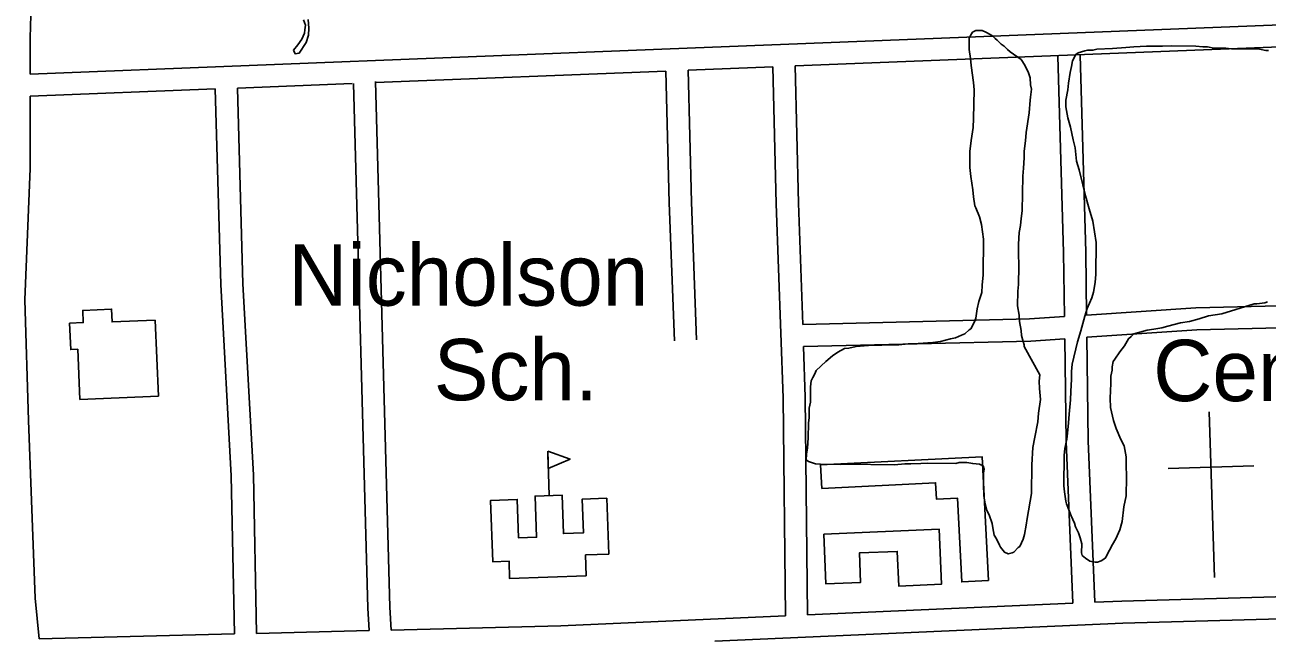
# Model space of a CAD drawing. Extents: x 3313447 to 3351316, y 703786 to 729172.
# Drawn here: x 3329082 to 3330764, y 710192 to 711026 of the extents above; entities that cross this region are included whole.
import ezdxf

# ---------------------------------------------------------------- set-up
doc = ezdxf.new("R2010")
doc.units = 0
for name, color, linetype in [('V-BLDG-IDEN', 7, 'Continuous'), ('V-BLDG-OTLN', 7, 'Continuous'), ('V-ROAD-CNTR', 7, 'Continuous'), ('V-SITE-OTLN', 7, 'Continuous'), ('V-SITE-OTLN-IDEN', 7, 'Continuous'), ('V-SITE-VEGE', 7, 'Continuous'), ('V-TOPO-SHOR', 7, 'Continuous')]:
    doc.layers.add(name, color=color, linetype=linetype)

msp = doc.modelspace()

# ---------------------------------------------------------------- linework, layer by layer
at = {"layer": 'V-BLDG-OTLN'}
msp.add_line((3329792.1, 710388.8), (3329790, 710448.8), dxfattribs=at)
for points in [[(3329258.6, 710626.4), (3329200.3, 710623.9), (3329199.6, 710641.3), (3329160.6, 710639.6), (3329161.3, 710623), (3329142.9, 710622.2), (3329144.5, 710586.5), (3329154, 710586.9), (3329156.9, 710519.1), (3329263, 710523.6)], [(3329790, 710448.8), (3329820.4, 710438.3), (3329790.8, 710425.7)], [(3330161, 710398.5), (3330315, 710406.3), (3330316.2, 710384.1), (3330344.7, 710385.5), (3330350.5, 710272), (3330386.5, 710273.9), (3330378, 710441.5), (3330159.4, 710430.4)], [(3329842.3, 710280.1), (3329738.5, 710276.4), (3329737.7, 710300.1), (3329715.7, 710299.3), (3329712.7, 710382.3), (3329748.7, 710383.6), (3329750.6, 710331.5), (3329774.9, 710332.4), (3329773, 710388.1), (3329809.4, 710389.4), (3329811.2, 710337.4), (3329838.5, 710338.4), (3329836.9, 710384.1), (3329869.9, 710385.3), (3329872.6, 710309.6), (3329841.3, 710308.5)], [(3330163.7, 710336.8), (3330320, 710343.3), (3330323.1, 710268.9), (3330265.1, 710266.4), (3330263.1, 710313.3), (3330211.9, 710311.2), (3330213.6, 710271.2), (3330166.5, 710269.3)]]:
    msp.add_lwpolyline(points, close=True, dxfattribs=at)
at = {"layer": 'V-ROAD-CNTR'}
for points in [[(3329089.4, 710959.4), (3329089.3, 711008.6), (3329093.9, 711162.6), (3329114.9, 711278.5), (3329148.8, 711371.5), (3329212.7, 711502.2), (3329303.4, 711601.8), (3329400.3, 711677.6), (3329487.9, 711723.5), (3329561.8, 711736.9), (3329654.7, 711724.8), (3329712.1, 711704.3), (3329765.7, 711668.2), (3329810.5, 711628.4), (3329839.1, 711600.8), (3329901.9, 711553.6)], [(3329089.4, 710959.4), (3329978.8, 710994.7), (3331252.6, 711044.7)], [(3330124.9, 710970.4), (3331253.5, 711014.7)], [(3330489.4, 710631.1), (3330488.3, 710717.9), (3330480.7, 710983.8)], [(3330519.4, 710633.1), (3330518.3, 710718.5), (3330510.7, 710985)], [(3329557.1, 710947.9), (3329950, 710963.5)], [(3329950, 710963.5), (3329954.5, 710785), (3329961.5, 710598.5)], [(3329980, 710964.7), (3330094.9, 710969.2)], [(3329980, 710964.7), (3329984.5, 710786), (3329991.5, 710599.6)], [(3330111.9, 710226), (3330108.7, 710521.2), (3330099.4, 710783.6), (3330094.9, 710969.2)], [(3330135.2, 710620.6), (3330129.4, 710784.5), (3330124.9, 710970.4)], [(3329370, 710940.5), (3329525.5, 710946.7)], [(3329548.3, 710206.1), (3329546.6, 710236.5), (3329527, 710946.6)], [(3329578.3, 710206.8), (3329576.5, 710237.7), (3329556.9, 710949.2)], [(3329101.5, 710194.9), (3329096.3, 710250.1), (3329087.1, 710490.4), (3329082.3, 710654), (3329089.7, 710831.4), (3329089.5, 710929.4)], [(3329089.5, 710929.4), (3329340, 710939.3)], [(3329366, 710201.5), (3329361.7, 710415.6), (3329347.4, 710674.4), (3329340, 710939.3)], [(3329396, 710202.2), (3329391.7, 710416.7), (3329377.4, 710675.6), (3329370, 710940.5)], [(3330519.4, 710633.1), (3330667.2, 710643.1), (3330892.3, 710648.4)], [(3330135.2, 710620.6), (3330442.4, 710628), (3330489.4, 710631.1)], [(3330519.8, 710603.1), (3330668.5, 710613.1), (3330893, 710618.4)], [(3330136.3, 710590.6), (3330443.8, 710598), (3330489.8, 710601.1)], [(3330500.8, 710243.2), (3330491.7, 710462.2), (3330489.8, 710601.1)], [(3330530.8, 710244.5), (3330521.7, 710463), (3330519.8, 710603.1)], [(3330141.9, 710227.3), (3330138.7, 710521.9), (3330136.3, 710590.6)], [(3330530.8, 710244.5), (3330567.3, 710246.1), (3331175.4, 710263), (3331283.4, 710266.7)], [(3330016.2, 710191.7), (3330568.3, 710216.1), (3331176.4, 710233), (3331690.7, 710250.7)], [(3330141.9, 710227.3), (3330500.8, 710243.2)], [(3329578.3, 710206.8), (3329808, 710212.6), (3330111.9, 710226)], [(3329101.5, 710194.9), (3329366, 710201.5)], [(3329396, 710202.2), (3329548.3, 710206.1)]]:
    msp.add_lwpolyline(points, dxfattribs=at)
at = {"layer": 'V-SITE-OTLN'}
for p, q in [((3330692.6, 710277.7), (3330685.5, 710502.1)), ((3330745.9, 710429.1), (3330629.9, 710425.5))]:
    msp.add_line(p, q, dxfattribs=at)
at = {"layer": 'V-SITE-VEGE'}
for points in [[(3330365.7, 710887.2), (3330366.6, 710899.1), (3330367.1, 710938.3), (3330366.5, 710948), (3330363.1, 710971), (3330362.5, 710980.7), (3330360.5, 710992.5), (3330360.7, 711008.1), (3330362.2, 711011.8), (3330365.2, 711016.2), (3330369.7, 711018.4), (3330377.9, 711018.3), (3330383, 711016), (3330388.9, 711012.9), (3330392.6, 711010.6), (3330395.5, 711007.6), (3330398.5, 711005.4), (3330403.6, 711000.1), (3330408, 710997.1), (3330412.4, 710992.6), (3330416, 710989.6), (3330430.7, 710979), (3330435.8, 710971.5), (3330440.8, 710961.1), (3330443, 710954.4), (3330443.6, 710944.7), (3330445, 710938.8), (3330443.4, 710928.4), (3330443.3, 710924), (3330441.6, 710906.9), (3330437.5, 710880.3), (3330436.6, 710869.2), (3330434.9, 710855.1), (3330434.8, 710846.2), (3330433.9, 710832.2), (3330433, 710821.1), (3330432.3, 710774.4), (3330430.7, 710764), (3330429.9, 710754.4), (3330428.2, 710744.8), (3330427.3, 710729.2), (3330427.1, 710717.4), (3330427.6, 710699.6), (3330427.3, 710674.4), (3330426.4, 710665.5), (3330426.1, 710645.5), (3330428.2, 710632.9), (3330428.8, 710624.7), (3330430.9, 710612.1), (3330431.5, 710605.4), (3330433.6, 710597.2), (3330435, 710592.7), (3330435, 710590.5), (3330456, 710552.4)], [(3330554.7, 710994.3), (3330572.5, 710995.6), (3330583.6, 710996.2), (3330600.7, 710997.4), (3330622.2, 710997.1), (3330634.8, 710997.7), (3330667.4, 710997.2), (3330677, 710996.4), (3330683, 710996.3), (3330691.8, 710994.7), (3330708.1, 710994.5), (3330715.5, 710993.6), (3330753.3, 710993.1), (3330762.2, 710991.5), (3330765.9, 710991.4)], [(3330702.5, 710635), (3330684.6, 710632.3), (3330672, 710628), (3330658.6, 710624.5), (3330646.7, 710622.5), (3330629.6, 710618.2), (3330621.4, 710616.1), (3330610.3, 710614.1), (3330601.4, 710612.7), (3330583.5, 710607.8), (3330579.7, 710604.1), (3330576, 710601.2), (3330570.7, 710591.6), (3330564.6, 710583.5), (3330557.8, 710573.3), (3330555.6, 710570.3), (3330554, 710562.9), (3330553.9, 710558.5), (3330552.3, 710550.4), (3330552.2, 710540.7), (3330551.2, 710520.7), (3330551.7, 710508.1), (3330555.9, 710490.3), (3330559.5, 710479.8), (3330566, 710464.9), (3330570.3, 710456), (3330573.1, 710441.1), (3330572.9, 710430.7), (3330573.4, 710413.7), (3330573.1, 710388.5), (3330569.9, 710373.7), (3330567.4, 710353.7), (3330564.3, 710342.6), (3330558.9, 710330.1), (3330554.4, 710322.8), (3330550.6, 710314.7), (3330548.3, 710311), (3330545.3, 710305.1), (3330543, 710302.9), (3330539.3, 710300.7), (3330534.1, 710298.6), (3330531.1, 710298.6), (3330523.7, 710300.2), (3330517.8, 710304), (3330513.4, 710307.8), (3330512.7, 710311.5), (3330512.9, 710323.3), (3330510.8, 710331.5), (3330508.6, 710338.2), (3330504.3, 710346.4), (3330502.9, 710351.6), (3330498.6, 710361.3), (3330496.4, 710367.3), (3330492.1, 710377.7), (3330491.5, 710381.4), (3330489.4, 710394.1), (3330488.8, 710402.2), (3330489.3, 710443), (3330490.2, 710452.6), (3330492.6, 710465.2), (3330493.5, 710473.3), (3330495.1, 710487.4), (3330496, 710499.2), (3330497.8, 710518.5), (3330497.9, 710529.6), (3330498.9, 710546.6), (3330499, 710557), (3330499.9, 710566.6), (3330507, 710596.9), (3330511.7, 710611.7), (3330517.1, 710631.6), (3330520.2, 710642), (3330526.4, 710656.7), (3330528.7, 710664.1), (3330531.1, 710677.4), (3330532, 710688.5), (3330532.6, 710731.5), (3330527.8, 710760.5), (3330522.8, 710776.8), (3330517.9, 710794.7), (3330514.4, 710809.6), (3330509.5, 710829.7), (3330505.9, 710841.6), (3330503.9, 710859.4), (3330501.1, 710870.5), (3330497.6, 710887.6), (3330494.1, 710900.3), (3330491.4, 710915.1), (3330491.5, 710924), (3330493.9, 710938.1), (3330494.8, 710947), (3330497.2, 710961.8), (3330498.8, 710969.9), (3330500.4, 710977.3), (3330504.9, 710986.1), (3330507.9, 710988.3), (3330516.9, 710991.1), (3330520.6, 710991.8), (3330528, 710991.7), (3330533.2, 710993.1), (3330554.7, 710994.3)], [(3330456, 710552.4), (3330455.1, 710543.5), (3330455.7, 710533.9), (3330457, 710519.1), (3330454.5, 710500.6), (3330453.6, 710488.7), (3330449.6, 710468), (3330446.5, 710454), (3330445.4, 710430.3), (3330444.9, 710391.7), (3330439.2, 710357.7), (3330437.6, 710348.8), (3330435.2, 710336.3), (3330433.7, 710329.6), (3330429.1, 710320), (3330426.8, 710318.6), (3330420.8, 710312), (3330418.6, 710311.3), (3330413.4, 710309.9), (3330408.2, 710312.2), (3330403.1, 710318.9), (3330401.7, 710321.9), (3330397.4, 710330.1), (3330394.5, 710335.3), (3330392.4, 710345), (3330391.7, 710350.9), (3330387.4, 710362.9), (3330384.5, 710368.8), (3330381.7, 710380), (3330380.4, 710388.9), (3330379.8, 710403.7), (3330380, 710419.3), (3330380.9, 710424.5), (3330379.4, 710428.9), (3330374.3, 710431.2), (3330365.4, 710432.1), (3330357.3, 710433.7), (3330346.9, 710433.8), (3330342.4, 710432.4), (3330303.9, 710432.9), (3330295, 710432.3), (3330281.6, 710431.8), (3330273.5, 710431.9), (3330259.4, 710430.6), (3330194.9, 710431.5), (3330186, 710430.8), (3330159.3, 710431.2), (3330152.7, 710432), (3330143.1, 710435.1), (3330140.1, 710437.4), (3330140.2, 710444.8), (3330141.8, 710453), (3330142.8, 710467), (3330143, 710487), (3330143.9, 710494.4), (3330144, 710507), (3330145.6, 710515.2), (3330145.9, 710535.9), (3330146.8, 710544.1), (3330149.1, 710548.5), (3330151.4, 710553.6), (3330153.6, 710558), (3330166.4, 710570.5), (3330175.4, 710577.8), (3330182.9, 710582.8), (3330191.9, 710587.9), (3330197.8, 710588.6), (3330207.5, 710590.7), (3330229.7, 710592.6), (3330242.3, 710592.4), (3330257.9, 710592.9), (3330265.3, 710592.8), (3330277.9, 710594.1), (3330291.3, 710594.7), (3330311.3, 710595.9), (3330321.7, 710597.3), (3330335.1, 710600.8), (3330341.8, 710602.2), (3330350, 710605.8), (3330354.5, 710607.9), (3330360.5, 710613), (3330362.7, 710614.5), (3330367.3, 710623.3), (3330369.6, 710629.2), (3330371.2, 710641.8), (3330373.6, 710651.4), (3330377.5, 710663.9), (3330378.3, 710673.6), (3330379.3, 710687.6), (3330379.9, 710735.8), (3330377.2, 710755.9), (3330374.4, 710766.3), (3330369.4, 710778.2), (3330368, 710781.2), (3330366.6, 710793.1), (3330365.3, 710802.7), (3330362.6, 710820.6), (3330361.3, 710833.2), (3330361.5, 710854.7), (3330363.2, 710869.5), (3330365.7, 710887.2)], [(3330764.2, 710651.2), (3330760.5, 710649.8), (3330750.1, 710648.5), (3330746.4, 710648.5), (3330702.5, 710635)]]:
    msp.add_lwpolyline(points, dxfattribs=at)
at = {"layer": 'V-TOPO-SHOR'}
for points in [[(3329465.7, 711033.3), (3329466.5, 711021.7), (3329466.4, 711012.1), (3329463.3, 711002.2), (3329453.8, 710987.9), (3329448.1, 710987), (3329445.9, 710991.7)], [(3329445.9, 710991.7), (3329451.7, 710999.2), (3329457.4, 711006.9), (3329460.8, 711014.8), (3329461.5, 711019.5), (3329462, 711025.7), (3329459.4, 711033.1)]]:
    msp.add_lwpolyline(points, dxfattribs=at)

# ---------------------------------------------------------------- texts
at = {"layer": 'V-BLDG-IDEN'}
for s, p in [('Nicholson', (3329438.9, 710645.9)), ('Sch.', (3329635.8, 710517.9))]:
    msp.add_text(s, height=83, dxfattribs=at).set_placement(p)
at = {"layer": 'V-SITE-OTLN-IDEN'}
msp.add_text('Cem.', height=83, dxfattribs=at).set_placement((3330609.6, 710516.7))

doc.saveas('drawing.dxf')
